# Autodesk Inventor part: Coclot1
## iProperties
Created: 2011-05
Part Number: Coclot1
Document SubType Name: Modeling
Designer: 904Chiaki
Density: 1 g/cm^3
Mass: 282.321 g
Surface Area: 676.471 cm^2
Volume: 282.321 cm^3
Author: 904Chiaki
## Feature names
1. Revolution1
2. Chamfer1
3. Chamfer2
4. Chamfer3
5. Chamfer4
6. Hole1
